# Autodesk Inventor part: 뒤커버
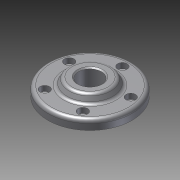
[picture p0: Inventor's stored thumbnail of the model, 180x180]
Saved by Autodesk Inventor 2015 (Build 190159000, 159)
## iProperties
Company: 한국ATC센터
Created: 2014-03
Part Number: 뒤커버
Document SubType Name: Modeling
Designer: KYOUNG IL JANG
Density: 1 g/cm^3
Material: 일반
Appearance: Default
Author: KYOUNG IL JANG
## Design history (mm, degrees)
sketch "스케치1"
  geometry: C1 r 20 at (0, 0); C2 r 35 at (0, 0); 1 further point
  constraints: 2 centre point, 2 coincident
  dimensions: "d0" = 40 diameter of C1; "d1" = 70 diameter of C2
extrude "돌출1" new body sketch "스케치1" distance "d2" = 5; taper "d3" = 0 deg
extrude "돌출2" join sketch "스케치1" distance "d4" = 8; taper "d5" = 0 deg
sketch "스케치2"
  geometry: C1 r 20 at (0, 0); 1 further point
  constraints: 1 centre point, 1 coincident
  dimensions: "d6" = 40 diameter of C1
extrude "돌출3" join sketch "스케치2" distance "d7" = 6; taper "d8" = -30 deg
sketch "스케치3"
  geometry: 2 further points
  constraints: 1 vertical alignment
  dimensions: "d9" = 27 distance of point (0, 0) point (0, 27)
hole "구멍1" sketch "스케치3" at (0, 27) diameter "d10" = 4.5; stored, may be unused: countersink angle "d14" = 90 deg, drill point angle "d16" = 118 deg; dims "d11" = 6, "d12" = 8, "d13" = 4.4, "d15" = 8
hole "구멍2" diameter "d22" = 19; stored, may be unused: countersink angle "d26" = 90 deg, drill point angle "d28" = 118 deg; dims "d20" = 10, "d21" = 10, "d23" = 6, "d24" = 30, "d25" = 3, "d27" = 8
fillet "모깎기1" dims "d29" = 3
chamfer "모따기1" distance "d30" = 1; stored, may be unused: second distance "d31" = 2, angle "d32" = 45 deg
node "솔리드1"
pattern_circular "원형 패턴1" dims angle "d18" = 360 deg
